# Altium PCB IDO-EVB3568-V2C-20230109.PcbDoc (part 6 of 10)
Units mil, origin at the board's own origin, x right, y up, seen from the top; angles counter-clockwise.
Board outline 5318 x 3544 mil, 2 copper layers (TOP, BOTTOM), stack 6.8 mil thick; 790 components, 626 nets, 2890 pads, 1922 vias.
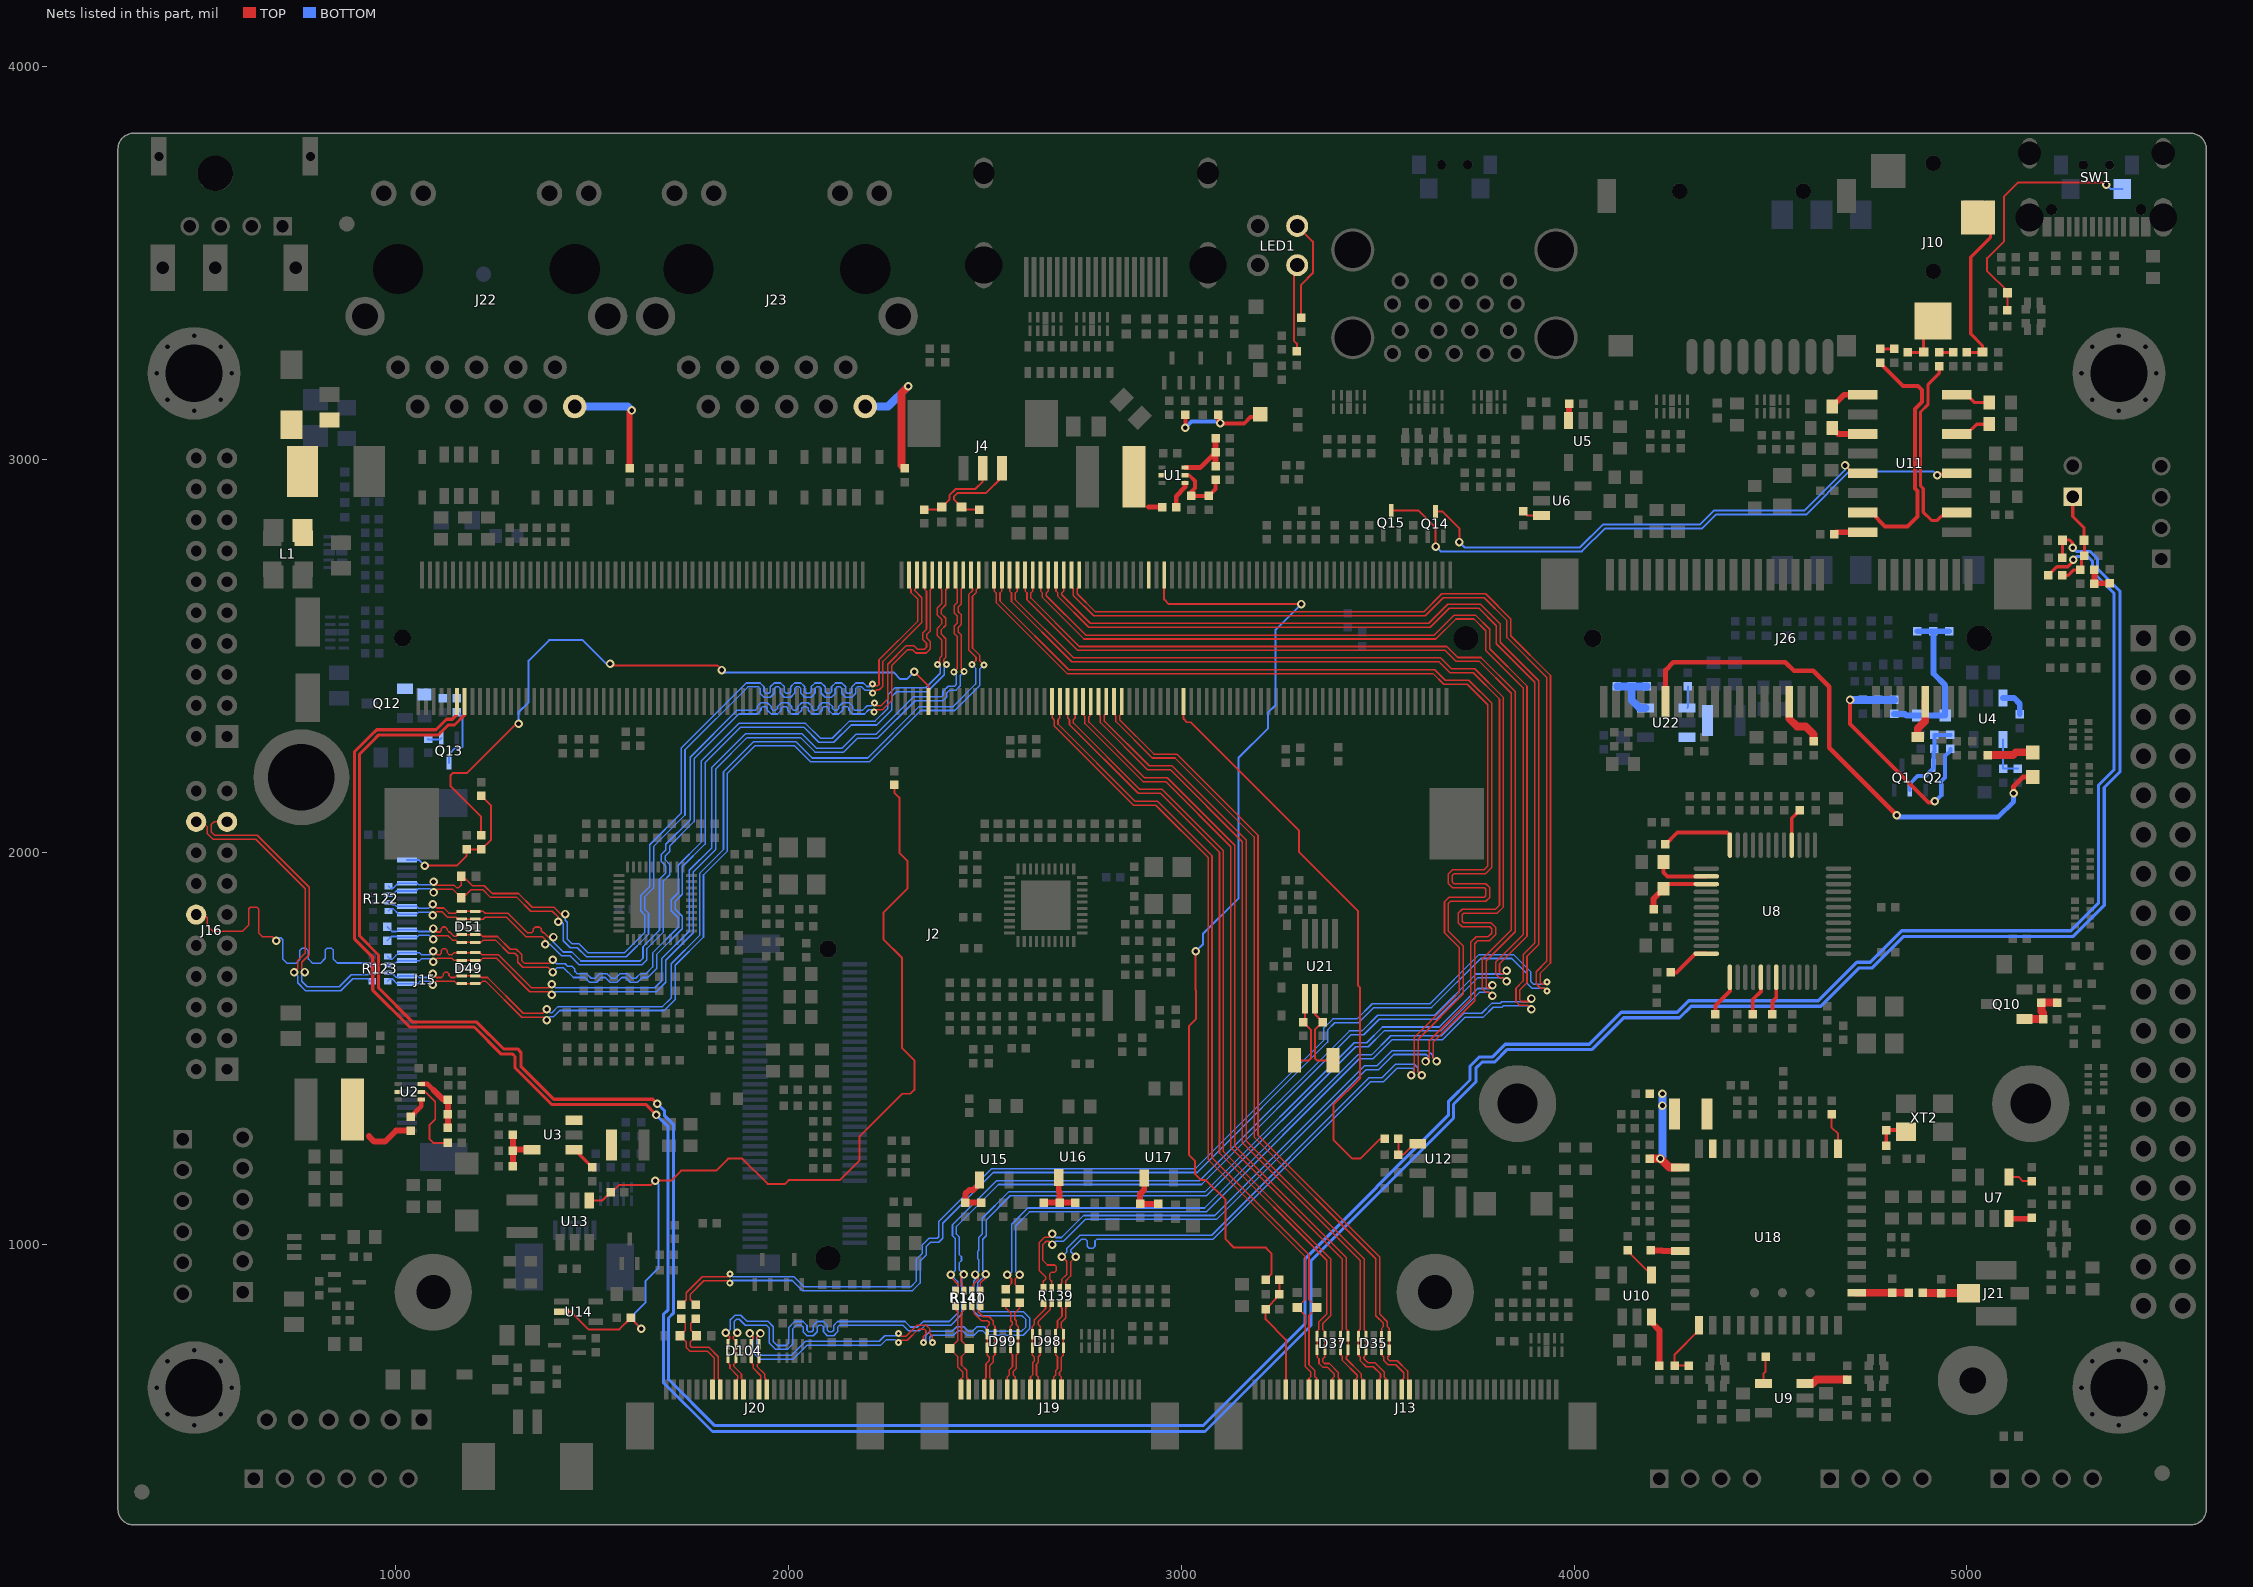
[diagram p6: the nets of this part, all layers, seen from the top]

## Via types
v1: diameter 21.65, hole 11.81, TOP to BOTTOM, 1878 vias
v2: diameter 17.72, hole 7.87, TOP to BOTTOM, 44 vias

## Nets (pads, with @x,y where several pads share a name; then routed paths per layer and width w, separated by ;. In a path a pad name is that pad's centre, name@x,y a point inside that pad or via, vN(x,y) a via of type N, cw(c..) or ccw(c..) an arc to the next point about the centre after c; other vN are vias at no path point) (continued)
LVDS_TX0_D2P: J16.12 R123.7 | length 771.1
  TOP w4: J16.12@491.26,1841.3 511.7,1841.3 519.63,1833.37 519.63,1813.37 534,1799 609,1799 625,1815 625,1856 629,1860 645.86,1860 650,1855.86 650,1795 660,1785 685,1785 v1(695,1775)
  BOTTOM w4: v1(695,1775) 702.35,1782.35 706.5,1782.35 711.93,1776.93 711.93,1727.93 722.36,1717.5 745.14,1717.5 755,1727.36 755,1750 760,1755 771,1755 777,1749 777,1728 787.5,1717.5 807.5,1717.5 820,1730 820,1751 824,1755 835.86,1755 840,1750.86 840,1728.36 850.36,1718 929,1718 934.16,1712.84 R123.7@939.32,1712.84
LVDS_TX0_D3N: J16.17 R123.6 | length 823.6
  TOP w4: J16.17@570,2077.52 536.52,2077.52 529.83,2070.83 529.83,2051.32 538.14,2043 647,2043 779,1911 779,1739 760,1720 760,1703 v1(768,1695)
  BOTTOM w4: v1(768,1695) 768,1694 760,1686 760,1671.5 774,1657.5 855.5,1657.5 886,1688 928,1688 933.16,1693.16 R123.6@939.32,1693.16
LVDS_TX0_D3P: J16.18 R123.5 | length 826.6
  TOP w4: J16.18@491.26,2077.52 506.48,2077.52 519.83,2064.17 519.83,2047.17 534,2033 642.86,2033 769,1906.86 769,1743.14 750,1724.14 750,1704.29 v1(740.36,1694.65)
  BOTTOM w4: v1(740.36,1694.65) 750,1685 750,1667.36 769.86,1647.5 859.64,1647.5 890.14,1678 928,1678 934.5,1671.5 R123.5@939.32,1671.5
MIC1_INN: C66.2 D97.2 J2.250 | length 8025.6
  TOP w8: 935.07,2296.39 894,2255.31 894,1780 941,1733 941,1649 1035,1555 1199,1555 1268,1486 1297,1486 1303,1480 1303,1451 1396,1358 1636,1358 v1(1663,1331) ; 935.08,2296.39 950.69,2312 1015.31,2312 1102,2312 1128.5,2338.5 1143.5,2338.5 1155.11,2350.11 J2.250@1155.11,2383.58 ; C66.2@5243.72,2750 5243.9,2750.18 D97.2@5243.9,2795 5262,2795 5270,2787 v1(5270,2775)
  BOTTOM w8: v1(1663,1331) 1693,1301 1693,835 1681,823 1681,649.86 1805.86,525 3060,525 3330,795 3330,960 3693,1323 3693,1358 3750,1415 3750,1450 3766,1466 3798,1466 3830,1498 4046,1498 4126.5,1578.5 4268.5,1578.5 4298,1608 4628,1608 4725,1705 4758,1705 4838,1785 5270,1785 5350,1865 5350,2165 5390,2205 5390,2665 5333,2722 5333,2747 5314,2766 5279,2766 v1(5270,2775)
MIC1_INP: C64.2 J2.248 | length 7964.5
  TOP w8: J2.248@1174.8,2383.58 1174.8,2349.8 1149,2324 1133.24,2324 1108.24,2299 1009.92,2299 956.08,2299 940.46,2283.38 907,2249.93 907,1787 955.5,1738.5 955.5,1654.5 1041.82,1568.18 1204.82,1568.18 1273.81,1499.19 1309.81,1499.19 1318,1491 1318,1455 1402,1371 1654,1371 v1(1665,1360) ; C64.2@5207.28,2705 5229.28,2727 5257,2727 5271,2741 v1(5271,2745)
  BOTTOM w8: v1(1665,1360) 1684,1341 1684,1329 1707,1306 1707,827 1694,814 1694,658.07 1812.07,540 3055,540 3315,800 3315,965 3680,1330 3680,1365 3735,1420 3735,1455 3759,1479 3792.61,1479 3824.61,1511 4039,1511 4120.49,1592.49 4262.49,1592.49 4292,1622 4622,1622 4720,1720 4754,1720 4834,1800 5265,1800 5335,1870 5335,2170 5375,2210 5375,2660 5320,2715 5320,2741 5308,2753 5279,2753 v1(5271,2745)
MIPI_CSI_CLK0N: D99.1 D99.10 J19.17 R148.2 | length 236.4
  TOP w4: J19.17@2576.42,632.01 2576.42,663.84 2571.57,668.68 2571.57,677.43 2580,685.86 2580,720 2584.37,724.37 D99.10@2584.37,737.78 D99.1@2584.37,772.22 2584.37,792.44 2579.53,797.28 2579.53,807.08 2575.5,811.11 2575.5,826.62 2588,839.12 R148.2@2588,852.28
MIPI_CSI_CLK0P: D99.2 D99.9 J19.18 R147.2 | length 236.9
  TOP w4: R147.2@2553,852.28 2553,839 2553.12,839 2565.5,826.62 2565.5,806.96 2569.53,802.94 2569.53,797.28 2564.68,792.43 D99.2@2564.68,772.22 D99.9@2564.68,737.78 2564.68,725.32 2570,720 2570,690 2561.57,681.58 2561.57,668.68 2556.73,663.84 J19.18@2556.73,632.01
MIPI_CSI_CLK1N: D105.1 J20.17 R158.2 | length 255.6
  TOP w4: R158.2@1763,812.28 1751,800.28 1751,783.1 D105.1@1765.1,769 1749,752.9 1749,743 1753,739 1797.45,739 1820.87,715.59 1820.87,660.13 1825.71,655.29 J20.17@1825.71,632.01
MIPI_CSI_CLK1P: D106.1 J20.18 R157.2 | length 255.2
  TOP w4: R157.2@1726,812.28 1726,812 1737,801 1737,783.1 D106.1@1722.9,769 1739,752.9 1739,738.86 1748.86,729 1793.31,729 1810.87,711.44 1810.87,659.87 1806.02,655.02 J20.18@1806.02,632.01
MIPI_CSI_D0N: D98.1 D98.10 J19.11 R139.8 | length 234.4
  TOP w4: J19.11@2694.53,632.01 2694.53,663.84 2689.69,668.68 2689.69,675.54 2694.53,680.38 2694.53,714.53 2699.37,719.37 D98.10@2699.37,737.78 D98.1@2699.37,772.22 2699.37,784.63 2694.53,789.47 2694.53,802.94 2706,814.41 2706,840 2711.5,845.5 R139.8@2711.5,851.32
MIPI_CSI_D0P: D98.2 D98.9 J19.12 R139.7 | length 234.6
  TOP w4: J19.12@2674.84,632.01 2674.84,663.84 2679.69,668.68 2679.69,679.69 2684.53,684.53 2684.53,715.47 2679.68,720.32 D98.9@2679.68,737.78 D98.2@2679.68,772.22 2679.68,784.68 2684.53,789.53 2684.53,807.08 2696,818.55 2696,839 2689.84,845.16 R139.7@2689.84,851.32
MIPI_CSI_D1N: D98.4 D98.7 J19.14 R139.6 | length 241.4
  TOP w4: J19.14@2635.47,632.01 2635.47,663.84 2631,668.31 2631,696 2635.47,700.48 2635.47,715.48 2640.32,720.32 D98.7@2640.32,737.78 D98.4@2640.32,772.22 2640.32,792.44 2635.47,797.28 2635.47,804.86 2666,835.38 2666,847.16 R139.6@2670.16,851.32
MIPI_CSI_D1P: D98.5 D98.6 J19.15 R139.5 | length 241.4
  TOP w4: J19.15@2615.79,632.01 2615.79,663.84 2621,669.05 2621,700.14 2625.47,704.62 2625.47,714.52 2620.63,719.37 D98.6@2620.63,737.78 D98.5@2620.63,772.22 2620.63,792.43 2625.47,797.28 2625.47,809 2654,837.52 2654,845.82 R139.5@2648.5,851.32
MIPI_CSI_D2N: D99.4 D99.7 J19.20 R140.8 | length 248.6
  TOP w4: R140.8@2488.5,844.32 2488.5,840.5 2482.87,834.87 2482.87,829.21 2495.14,816.94 2510.62,816.94 2520.47,807.08 2520.47,797.28 2525.32,792.44 D99.4@2525.32,772.22 D99.7@2525.32,737.78 2525.32,720.32 2520.47,715.48 2520.47,701.33 2512.52,693.38 2512.52,662.48 2517.36,657.64 J19.20@2517.36,632.01
MIPI_CSI_D2N_: D104.1 D104.10 J20.11 R141.5 | length 1209
  TOP w4: v1(1928.17,774.65) 1919.53,766 1919.53,761.85 1924.37,757 D104.1@1924.37,747.22 D104.10@1924.37,712.78 1924.37,699.37 1919.53,694.53 1919.53,690.62 1938.98,671.16 1938.98,661.02 1943.82,656.18 J20.11@1943.82,632.01 ; v2(2280,774.72) 2280,773.14 2286,767.14 2298,767.14 2326.55,795.69 2349.78,795.69 2359.64,785.84 2359.64,773.68 2366,767.32 v2(2366,751.86)
  BOTTOM w4: v1(1928.17,774.65) 1919,765.48 1919,731 1931,719 2006.86,719 2042.86,755 2230.64,755 2244.64,769 2273,769 2278.72,774.72 v2(2280,774.72) ; v2(2366,751.86) 2363.14,751.86 2359,756 2359,765 2364,770 2419.98,770 2431.98,782 2441.84,782 2453.84,770 2471.98,770 2483.98,782 2493.84,782 2505.84,770 2597,770 2614,787 2614,795.28 2614,814 2598.19,829.81 2556.55,829.81 ; R141.5@2486.5,845.32 2486.5,833.81 2490.48,829.83 2499.98,829.83 ; 2500,829.81 2533.45,829.81 ; 2533.47,829.83 2556.53,829.83
MIPI_CSI_D2P: D99.5 D99.6 J19.21 R140.7 | length 248.8
  TOP w4: R140.7@2466.84,844.32 2466.84,838.16 2472.87,832.13 2472.87,825.07 2491,806.94 2506.47,806.94 2510.47,802.94 2510.47,797.28 2505.63,792.43 D99.5@2505.63,772.22 D99.6@2505.63,737.78 2505.63,719.37 2510.47,714.52 2510.47,705.48 2502.52,697.52 2502.52,662.52 2497.68,657.68 J19.21@2497.68,632.01
MIPI_CSI_D2P_: D104.2 D104.9 J20.12 R141.6 | length 1211.6
  TOP w4: v1(1900.88,774.65) 1909.53,766 1909.53,762 1904.68,757.16 D104.2@1904.68,747.22 D104.9@1904.68,712.78 1904.68,700.32 1909.53,695.47 1909.53,686.47 1928.98,667.02 1928.98,658.98 1924.13,654.13 J20.12@1924.13,632.01 ; v2(2280,752) 2285.14,757.14 2302.14,757.14 2330.69,785.69 2345.64,785.69 2349.64,781.69 2349.64,773.68 2343.28,767.32 v2(2343.28,751.86)
  BOTTOM w4: v1(1900.88,774.65) 1909,766.53 1909,726.86 1926.86,709 2011,709 2047,745 2234.79,745 2248.79,759 2271,759 2278,752 v2(2280,752) ; v2(2343.28,751.86) 2349,757.58 2349,769.14 2359.86,780 2415.84,780 2427.84,792 2445.98,792 2457.98,780 2467.84,780 2479.84,792 2497.98,792 2509.98,780 2592.86,780 2604,791.14 2604,809.86 2594.05,819.81 2552.41,819.81 ; R141.6@2464.84,845.32 2464.84,838.16 2483.17,819.83 2495.84,819.83 ; 2495.86,819.81 2537.59,819.81 ; 2537.61,819.83 2552.39,819.83
MIPI_CSI_D3N: D100.1 J19.23 R140.6 | length 239.5
  TOP w4: R140.6@2447.16,844.32 2447.16,834.16 2440,827 2440,756 2459.9,736.1 D100.1@2460,736.1 2440,716.1 2440,694.14 2453.47,680.68 2453.47,661.54 2458.31,656.69 J19.23@2458.31,632.01
MIPI_CSI_D3N_: D104.4 D104.7 J20.14 R141.7 | length 998.1
  TOP w4: v1(1869.32,776.43) 1859.27,766.38 1859.27,760.73 1865.32,754.68 D104.4@1865.32,747.22 D104.7@1865.32,712.78 1865.32,700.32 1860.47,695.48 1860.47,690.67 1879.92,671.22 1879.92,660.08 1884.76,655.24 J20.14@1884.76,632.01
  BOTTOM w4: v1(1869.32,776.43) 1869.32,778.68 1861.45,786.54 1861.45,805.31 1867.24,811.09 1873.89,811.09 1889.48,795.5 1943.36,795.5 1951,787.86 1951,749.86 1966.86,734 1997.14,734 2010,746.86 2010,785.86 2019.14,795 2032.59,795 2036.59,791 2036.59,778.86 2046.45,769 2062.74,769 2072.59,778.86 2072.59,791 2076.59,795 2084.59,795 2088.59,791 2088.59,778.86 2098.45,769 2114.74,769 2124.59,778.86 2124.59,791 2128.59,795 2292,795 2306,781 2333,781 2347,795 2412.69,795 2441,823.31 2441,835 2445.16,839.16 R141.7@2445.16,845.32
MIPI_CSI_D3P: D101.1 J19.24 R140.5 | length 238.4
  TOP w4: R140.5@2425.5,844.32 2425.5,834.5 2430,830 2430,756 2410.1,736.1 D101.1@2410,736.1 2430,716.1 2430,690 2443.47,676.53 2443.47,663.46 2438.62,658.62 J19.24@2438.62,632.01
MIPI_CSI_D3P_: D104.5 D104.6 J20.15 R141.8 | length 1001.7
  TOP w4: v1(1839.78,776.32) 1849.27,766.83 1849.27,760.27 1845.63,756.63 D104.5@1845.63,747.22 D104.6@1845.63,712.78 1845.63,699.37 1850.47,694.52 1850.47,686.52 1869.92,667.08 1869.92,659.92 1865.08,655.08 J20.15@1865.08,632.01
  BOTTOM w4: v1(1839.78,776.32) 1842.88,776.32 1851.45,784.89 1851.45,809.46 1857.31,815.31 1863.09,821.09 1878.03,821.09 1893.63,805.5 1947.5,805.5 1961,792 1961,754 1971,744 1993,744 2000,751 2000,790 2015,805 2036.74,805 2046.59,795.14 2046.59,783 2050.59,779 2058.59,779 2062.59,783 2062.59,795.14 2072.45,805 2088.74,805 2098.59,795.14 2098.59,783 2102.59,779 2110.59,779 2114.59,783 2114.59,795.14 2124.45,805 2296.14,805 2310.14,791 2328.86,791 2342.86,805 2408.55,805 2431,827.45 2431,835 2423.5,842.5 R141.8@2423.5,845.32
MIPI_CSI_RX_CLK0N: J2.103 R148.1 | length 4034.2
  TOP w4: v1(2587.78,924.5) 2587.78,924 2577.39,913.61 2577.39,898.33 R148.1@2588,887.72 ; J2.103@2680.7,2706.42 2680.7,2665.14 2685.55,2660.3 2685.55,2651.45 2764,2573 3634,2573 3682.28,2621.28 3757.58,2621.28 3802,2576.86 3802,2530.86 3900,2432.86 3900,1769.14 3870,1739.14 3870,1672 3852,1654 3852,1619.86 3861.86,1610 3882,1610 v1(3891.5,1600.5)
  BOTTOM w4: v1(2587.78,924.5) 2584.5,924.5 2578,931 2578,1048.86 2613.14,1084 3063.14,1084 3453.14,1474 3488.14,1474 3537.07,1522.93 3665.8,1522.93 3723.04,1580.17 3769.17,1580.17 3794,1605 3816.14,1605 3820.14,1609 3883,1609 v1(3891.5,1600.5)
MIPI_CSI_RX_CLK0P: J2.101 R147.1 | length 4035.8
  TOP w4: R147.1@2553,887.72 2567.39,902.11 2567.39,913.61 v1(2557,924) ; J2.101@2700.39,2706.42 2700.39,2665.14 2695.55,2660.3 2695.55,2655.6 2768.14,2583 3629.86,2583 3678.13,2631.28 3761.72,2631.28 3764.65,2628.35 3812,2581 3812,2535 3910,2437 3910,1765 3880,1735 3880,1667.86 3862,1649.86 3862,1624 3866,1620 3884,1620 v1(3891.5,1627.5)
  BOTTOM w4: v1(2557,924) 2561,924 2568,931 2568,1053 2609,1094 3059,1094 3449,1484 3484,1484 3532.93,1532.93 3661.65,1532.93 3718.9,1590.17 3765.03,1590.17 3789.86,1615 3812,1615 3816,1619 3883,1619 v1(3891.5,1627.5)
MIPI_CSI_RX_CLK1N: J2.99 R158.1 | length 4965.9
  TOP w4: R158.1@1763,847.72 1749,861.72 1749,874 1784,909 1843.46,909 v2(1850,903) ; J2.99@2720.07,2706.42 2720.07,2675.84 2724.91,2671 2724.91,2654.09 2777,2602 3621,2602 3667,2648 3771,2648 3829,2590 3829,2546.86 3930,2445.86 3930,1722.14 3903.5,1695.64 3903.5,1665.36 3914.86,1654 3925,1654 3930.97,1648.03 v2(3930.97,1647)
  BOTTOM w4: v2(1850,903) 1856.5,909.5 2008.94,909.5 2034.61,883.83 2315.39,883.83 2334.5,902.94 2334.5,958.71 2350.5,974.71 2350.5,996.36 2361.14,1007 2382.14,1007 2392,1016.86 2392,1055.44 2521.06,1184.5 3040.06,1184.5 3372.17,1516.61 3372.17,1547.39 3390.29,1565.5 3451.08,1565.5 3490.08,1604.5 3637.06,1604.5 3762.06,1729.5 3841.36,1729.5 3880,1690.86 3880,1666.28 3892.73,1653.55 3908.99,1653.53 3925.48,1653.53 3930.97,1648.02 v2(3930.97,1647)
MIPI_CSI_RX_CLK1P: J2.97 R157.1 | length 4965.2
  TOP w4: R157.1@1726,847.72 1739,860.72 1739,878.14 1779.86,919 1844.59,919 v2(1851,926) ; J2.97@2739.76,2706.42 2739.76,2676 2734.91,2671.16 2734.91,2658.23 2781.14,2612 3616.86,2612 3662.86,2658 3775.14,2658 3839,2594.14 3839,2551 3940,2450 3940,1718 3913.5,1691.5 3913.5,1669.5 3919,1664 3926,1664 3931,1669 v2(3931,1670)
  BOTTOM w4: v2(1851,926) 1857.5,919.5 2013.08,919.5 2038.75,893.83 2311.25,893.83 2324.5,907.08 2324.5,962.86 2340.5,978.86 2340.5,1000.5 2357,1017 2378,1017 2382,1021 2382,1059.58 2516.92,1194.5 3035.92,1194.5 3362.17,1520.75 3362.17,1551.53 3386.14,1575.5 3446.94,1575.5 3485.94,1614.5 3632.92,1614.5 3757.92,1739.5 3845.5,1739.5 3890,1695 3890,1670.42 3896.87,1663.55 3909,1663.53 3924.51,1663.53 v2(3931,1670)
MIPI_CSI_RX_D0N: J2.119 R139.1 | length 3949.3
  TOP w4: J2.119@2523.22,2706.42 2523.22,2665.14 2528.06,2660.3 2528.06,2635.79 2708.86,2455 3640.86,2455 3667.86,2428 3727.86,2428 3780,2375.86 3780,1965 3770,1955 3689.86,1955 3680,1945.14 3680,1919.86 3689.86,1910 3771,1910 3775,1906 3775,1889 3771,1885 3680.86,1885 3670,1874.14 3670,1795 3708,1757 3708,1643 3593,1528 3593,1440 v1(3585,1432) ; R139.1@2711.5,890.68 2711.5,894.5 2705,901 2705,907.86 2717.81,920.67 2717.81,956.81 v1(2731.15,970.15)
  BOTTOM w4: v1(2731.15,970.15) 2718.5,982.79 2718.5,987.36 2746.14,1015 2755,1015 2760,1010 2760,997 2765.17,991.83 2774.83,991.83 2780,997 2780,1010 2785,1015 3081.14,1015 3482.14,1416 3515.14,1416 3549.14,1450 3589,1450 3593,1446 3593,1440 v1(3585,1432)
MIPI_CSI_RX_D0P: J2.117 R139.2 | length 3947.7
  TOP w4: J2.117@2542.91,2706.42 2542.91,2665.14 2538.06,2660.3 2538.06,2639.94 2713,2465 3645,2465 3672,2438 3732,2438 3790,2380 3790,1960.86 3774.14,1945 3694,1945 3690,1941 3690,1924 3694,1920 3775.14,1920 3785,1910.14 3785,1884.86 3775.14,1875 3685,1875 3680,1870 3680,1799.14 3718,1761.14 3718,1638.86 3603,1523.86 3603,1441 v1(3612,1432) ; R139.2@2689.84,890.68 2689.84,897.84 2695,903 2695,912 2707.81,924.81 2707.81,958.19 v1(2695.86,970.15)
  BOTTOM w4: v1(2695.86,970.15) 2708.5,982.79 2708.5,991.5 2742,1025 3077,1025 3478,1426 3511,1426 3545,1460 3593.14,1460 3603,1450.14 3603,1441 v1(3612,1432)
MIPI_CSI_RX_D1N: J2.115 R139.3 | length 3952.9
  TOP w4: J2.115@2562.59,2706.42 2562.59,2665.14 2567.43,2660.3 2567.43,2638.42 2720.86,2485 3655.86,2485 3683.86,2457 3743,2457 3810,2390 3810,1865 3800,1855 3715,1855 3705,1845 3705,1820 3715,1810 3785,1810 3790,1805 3790,1794 3781,1785 3750.86,1785 3737,1771.14 3737,1626.14 3631,1520.14 3631,1476.49 v1(3621.68,1467.16) ; R139.3@2670.16,890.68 2670.16,907.36 2664.33,913.19 2664.33,926.33 2669,931 2678,931 2681,934 2681,946 2678,949 2659,949 2647.5,960.5 2647.5,1001.36 2655.64,1009.5 2662.5,1009.5 v1(2671,1001)
  BOTTOM w4: v1(2671,1001) 2679,1009 2699,1009 2755,1065 3089.14,1065 3470.14,1446 3502,1446 3541,1485 3623.86,1485 3629.86,1479 3629.86,1475.34 v1(3621.68,1467.16)
MIPI_CSI_RX_D1P: J2.113 R139.4 | length 3955.3
  TOP w4: J2.113@2582.28,2706.42 2582.28,2665.14 2577.43,2660.3 2577.43,2642.57 2725,2495 3660,2495 3688,2467 3747.14,2467 3820,2394.14 3820,1860.86 3804.14,1845 3719.14,1845 3715,1840.86 3715,1824.14 3719.14,1820 3789.14,1820 3800,1809.14 3800,1789.86 3785.14,1775 3755,1775 3747,1767 3747,1622 3641,1516 3641,1476.49 v1(3649.65,1467.84) ; R139.4@2648.5,890.68 2648.5,907.37 2654.33,913.19 2654.33,918.53 2637.5,935.36 2637.5,1005.5 2651.5,1019.5 2662.5,1019.5 v1(2671,1028)
  BOTTOM w4: v1(2671,1028) 2680,1019 2694.86,1019 2750.86,1075 3085,1075 3466,1456 3497.86,1456 3536.86,1495 3628,1495 3639.86,1483.14 3639.86,1477.63 v1(3649.65,1467.84)
MIPI_CSI_RX_D2N: J2.111 R140.1 R141.4 | length 3991
  TOP w4: R140.1@2488.5,883.68 2488.07,884.11 2488.07,902.93 2499,913.86 2499,921.87 v1(2502.18,925.05) ; J2.111@2601.96,2706.42 2601.96,2665.14 2606.8,2660.3 2606.8,2643.2 2736,2514 3671.86,2514 3699.86,2486 3759,2486 3840,2405 3840,1802 3766,1728 3766,1653 3775.86,1643.14 3783.37,1643.14 v1(3792.16,1634.36)
  BOTTOM w4: R141.4@2486.5,884.68 2481,890.18 2481,903.87 v1(2502.18,925.05) 2502.18,928.18 2494,936.36 2494,1014.64 2502.83,1023.47 2502.83,1063.68 2564.14,1125 3064.14,1125 3444.14,1505 3476.14,1505 3516.14,1545 3661,1545 3759,1643 3783.51,1643 v1(3792.16,1634.36)
MIPI_CSI_RX_D2P: J2.109 R140.2 R141.3 | length 3990.8
  TOP w4: R140.2@2466.84,883.68 2470,886.84 2470,899 2482.35,911.35 2482.35,918.65 2476.35,924.65 v1(2475.53,924.65) ; J2.109@2621.65,2706.42 2621.65,2665.14 2616.8,2660.3 2616.8,2647.34 2740.14,2524 3676,2524 3704,2496 3763.14,2496 3850,2409.14 3850,1797.86 3776,1723.86 3776,1657.14 3780,1653.14 3783.66,1653.14 v1(3792.16,1661.65)
  BOTTOM w4: R141.3@2464.84,884.68 2464.84,888.84 2471,895 2471,908.01 2476.35,913.36 2476.35,923.83 v1(2475.53,924.65) 2484,933.12 2484,962.41 2481,965.41 2481,983.41 2484,986.41 2484,1018.79 2492.83,1027.61 2492.83,1067.83 2560,1135 3060,1135 3440,1515 3472,1515 3512,1555 3656.86,1555 3754.86,1653 3783.51,1653 v1(3792.16,1661.65)
MIPI_CSI_RX_D3N: J2.107 R140.3 R141.2 | length 4139.2
  TOP w4: v1(2446.22,924.82) 2445.82,924.82 2437.64,916.64 2437.64,907.36 2442,903 2442,895 2447.16,889.84 R140.3@2447.16,883.68 ; J2.107@2641.33,2706.42 2641.33,2665.14 2646.18,2660.3 2646.18,2648.82 2752,2543 3648,2543 3699,2594 3744.86,2594 3775,2563.86 3775,2514 3870,2419 3870,1790 3800,1720 3800,1690.16 3804.93,1685.23 3809.86,1680.3 3819.05,1680.3 v1(3828,1671.36)
  BOTTOM w4: R141.2@2445.16,884.68 2445.16,888.11 2440,893.26 2440,917.83 2446.22,924.04 v1(2446.22,924.82) 2434,937.04 2434,953.86 2440,959.86 2440,969.86 2434,975.86 2434,1020.78 2427.17,1027.61 2427.17,1047.17 2534,1154 3051.14,1154 3432.14,1535 3464.14,1535 3504.14,1575 3649.14,1575 3754.14,1680 3819.36,1680 v1(3828,1671.36)
MIPI_CSI_RX_D3P: J2.105 R140.4 R141.1 | length 4140.5
  TOP w4: v1(2413.04,924.04) 2415,922.08 2415,915.86 2432,898.86 2432,890.18 R140.4@2425.5,883.68 ; J2.105@2661.02,2706.42 2661.02,2665.14 2656.18,2660.3 2656.18,2652.97 2756.14,2553 3643.86,2553 3694.86,2604 3749,2604 3785,2568 3785,2518.14 3880,2423.14 3880,1785.86 3810,1715.86 3810,1694.3 3814,1690.3 3819.66,1690.3 v1(3828,1698.65)
  BOTTOM w4: R141.1@2423.5,884.68 2430,891.18 2430,907.08 v1(2413.04,924.04) 2424,935 2424,1016.64 2417.17,1023.47 2417.17,1051.32 2529.86,1164 2538.14,1164 3047,1164 3428,1545 3460,1545 3500,1585 3645,1585 3750,1690 3819.35,1690 v1(3828,1698.65)
MIPI_DSI_TX0_CLKN: D51.2 D51.9 J2.133 J15.27 R127.1 | length 2434.4
  TOP w4: v1(1094.64,1805.76) 1103.4,1797 1112,1797 1115,1800 1115,1805 1119.67,1809.67 1125.33,1809.67 1130,1805 1130,1802 1135,1797 1137.14,1797 1147.74,1786.4 1153.4,1786.4 1157.32,1790.32 D51.9@1167.78,1790.32 D51.2@1202.22,1790.32 1215.68,1790.32 1220.53,1785.47 1258.67,1785.47 1291.08,1753.06 1306.43,1753.06 1320.07,1739.42 1320.07,1724.08 1327.14,1717 1390,1717 v1(1399,1726) ; v2(2379.28,2478) 2385,2483.72 2385,2495 2390.27,2500.27 2390.27,2539.8 2378,2552.07 2378,2569.95 2390.27,2582.22 2390.27,2591.8 2378,2604.07 2378,2621.95 2390.27,2634.22 2390.27,2667.73 2385.43,2672.57 J2.133@2385.43,2706.42
  BOTTOM w4: R127.1@977.72,1810 989.61,1798.11 1001.11,1798.11 1005.95,1802.95 J15.27@1027.99,1802.95 1052.05,1802.95 1056.89,1798.11 1087,1798.11 v1(1094.64,1805.76) ; v1(1399,1726) 1409,1716 1431,1716 1437,1710 1448,1710 1455,1703 1455,1697 1461,1691 1485,1691 1497,1679 1506.86,1679 1518.86,1691 1537,1691 1549,1679 1558.86,1679 1570.86,1691 1589,1691 1601,1679 1610.86,1679 1622.86,1691 1637,1691 1653.5,1707.5 1653.5,1743.64 1719,1809.14 1719,1833 1701,1851 1701,1879 1719,1897 1719,1967 1777,2025 1777,2232 1873,2328 2043,2328 2081,2290 2110.86,2290 2154.86,2334 2220,2334 2252,2366 2252,2400.14 2270.86,2419 2349,2419 2386,2456 2386,2471.28 v2(2379.28,2478)
MIPI_DSI_TX0_CLKP: D51.1 D51.10 J2.131 J15.26 R126.1 | length 2434
  TOP w4: v1(1094.64,1778.46) 1103.18,1787 1133,1787 1143.6,1776.4 1152.6,1776.4 1158.37,1770.63 D51.10@1167.78,1770.63 D51.1@1202.22,1770.63 1216.63,1770.63 1221.47,1775.47 1254.53,1775.47 1286.94,1743.06 1302.29,1743.06 1310.07,1735.28 1310.07,1719.93 1323,1707 1387,1707 v1(1399,1695) ; v2(2402,2478) 2395,2485 2395,2490.86 2400.27,2496.13 2400.27,2543.95 2388,2556.22 2388,2565.8 2400.27,2578.07 2400.27,2595.95 2388,2608.22 2388,2617.8 2400.27,2630.07 2400.27,2668.27 2405.11,2673.11 J2.131@2405.11,2706.42
  BOTTOM w4: R126.1@977.72,1775 988.25,1785.53 1002.47,1785.53 1004.73,1783.27 J15.26@1027.99,1783.27 1053.27,1783.27 1058.11,1788.11 1085,1788.11 v1(1094.64,1778.46) ; v1(1399,1695) 1410,1706 1426.86,1706 1451.86,1681 1480.86,1681 1492.86,1669 1511,1669 1523,1681 1532.86,1681 1544.86,1669 1563,1669 1575,1681 1584.86,1681 1596.86,1669 1615,1669 1627,1681 1641.14,1681 1663.5,1703.36 1663.5,1739.5 1729,1805 1729,1837.14 1711,1855.14 1711,1874.86 1729,1892.86 1729,1962.86 1787,2020.86 1787,2227.86 1877.14,2318 2038.86,2318 2076.86,2280 2115,2280 2159,2324 2224.14,2324 2262,2361.86 2262,2396 2275,2409 2353.14,2409 2396,2451.86 2396,2472 v2(2402,2478)
MIPI_DSI_TX0_D0N: D53.1 J2.141 J15.33 R122.1 | length 2441.2
  TOP w4: v1(1095.64,1924.87) 1104.29,1916.22 1148.03,1916.22 1154.3,1909.95 1159.95,1909.95 1166.1,1916.1 D53.1@1166.1,1939 1170.57,1939 1194.57,1915 1225,1915 1245,1895 1312,1895 1347,1860 1402.14,1860 1419.5,1842.65 v1(1431.24,1842.65) ; v2(2212.92,2428.69) 2213.31,2428.69 2218.5,2423.5 2226.36,2423.5 2230,2427.14 2230,2490 2329,2589 2329,2644 2311.53,2661.47 2311.53,2669.47 2306.69,2674.31 J2.141@2306.69,2706.42
  BOTTOM w4: R122.1@980.68,1913.5 986.26,1907.92 991.92,1907.92 1005.06,1921.06 J15.33@1027.99,1921.06 1053.94,1921.06 1058.17,1916.83 1087.61,1916.83 v1(1095.64,1924.87) ; v1(1431.24,1842.65) 1431.24,1826.76 1436,1822 1436,1779 1448,1767 1466,1767 1489,1744 1582,1744 1633,1795 1633,1841 1623,1851 1623,1890 1646,1913 1646,2019 1726,2099 1726,2265 1892,2431 1927.19,2431 1937.05,2421.14 1937.05,2409 1941.05,2405 1949.05,2405 1953.05,2409 1953.05,2421.14 1962.91,2431 1979.19,2431 1989.05,2421.14 1989.05,2409 1993.05,2405 2001.05,2405 2005.05,2409 2005.05,2421.14 2014.91,2431 2031.19,2431 2041.05,2421.14 2041.05,2409 2045.05,2405 2053.05,2405 2057.05,2409 2057.05,2421.14 2066.91,2431 2083.19,2431 2093.05,2421.14 2093.05,2409 2097.05,2405 2105.05,2405 2109.05,2409 2109.05,2421.14 2118.91,2431 2135.19,2431 2145.05,2421.14 2145.05,2409 2149.05,2405 2157.05,2405 2161.05,2409 2161.05,2421.14 2170.91,2431 2190.14,2431 2199.14,2422 2206.23,2422 v2(2212.92,2428.69)
MIPI_DSI_TX0_D0P: D52.1 J2.139 J15.32 R122.2 | length 2433.3
  TOP w4: v1(1095.64,1897.58) 1104.29,1906.22 1143.88,1906.22 D52.1@1166.1,1884 1170.57,1884 1191.57,1905 1220.86,1905 1240.86,1885 1307.86,1885 1342.86,1850 1398,1850 1413,1835 v1(1413,1823) ; v2(2214,2406) 2216.95,2406 2224.45,2413.5 2230.5,2413.5 2240,2423 2240,2485.86 2339,2584.86 2339,2648.14 2321.53,2665.61 2321.53,2669.53 2326.37,2674.37 J2.139@2326.37,2706.42
  BOTTOM w4: R122.2@980.68,1891.84 990.84,1891.84 1000.38,1901.38 J15.32@1027.99,1901.38 1051.38,1901.38 1056.83,1906.83 1086.39,1906.83 v1(1095.64,1897.58) ; v1(1413,1823) 1420.86,1823 1426,1817.86 1426,1774.86 1443.86,1757 1461.86,1757 1484.86,1734 1586.14,1734 1643,1790.86 1643,1845.14 1633,1855.14 1633,1885.86 1656,1908.86 1656,2014.86 1736,2094.86 1736,2260.86 1896.14,2421 1923.05,2421 1927.05,2417 1927.05,2404.86 1936.91,2395 1953.19,2395 1963.05,2404.86 1963.05,2417 1967.05,2421 1975.05,2421 1979.05,2417 1979.05,2404.86 1988.91,2395 2005.19,2395 2015.05,2404.86 2015.05,2417 2019.05,2421 2027.05,2421 2031.05,2417 2031.05,2404.86 2040.91,2395 2057.19,2395 2067.05,2404.86 2067.05,2417 2071.05,2421 2079.05,2421 2083.05,2417 2083.05,2404.86 2092.91,2395 2109.19,2395 2119.05,2404.86 2119.05,2417 2123.05,2421 2131.05,2421 2135.05,2417 2135.05,2404.86 2144.91,2395 2161.19,2395 2171.05,2404.86 2171.05,2417 2175.05,2421 2186,2421 2195,2412 2208,2412 v2(2214,2406)
MIPI_DSI_TX0_D1N: D51.5 D51.6 J2.137 J15.30 R122.3 | length 2408.2
  TOP w4: v1(1093.65,1867.81) 1103.46,1858 1122,1858 1135,1845 1152,1845 1156.37,1849.37 D51.6@1167.78,1849.37 D51.5@1202.22,1849.37 1222.43,1849.37 1227.28,1844.53 1285.47,1844.53 1335,1795 1345,1795 1350,1800 1350,1805 1354.67,1809.67 1365.33,1809.67 1370,1805 1370,1800 1375,1795 1377,1795 1387.99,1784.01 v1(1401.01,1784.01) ; v2(2218,2380) 2225,2373 2235,2373 2252,2390 2252,2479 2299,2526 2319,2526 2327.57,2517.43 2346.28,2517.43 2350.9,2522.04 2350.9,2532.1 2341.5,2541.5 2341.5,2558.6 2350.9,2568 2350.9,2665.1 2346.06,2669.94 J2.137@2346.06,2706.42
  BOTTOM w4: R122.3@980.68,1872.16 984.84,1872.16 990,1867 996.24,1867 1001.24,1862.01 J15.30@1027.99,1862.01 1052.99,1862.01 1057.84,1857.16 1083,1857.16 v1(1093.65,1867.81) ; v1(1401.01,1784.01) 1400.1,1772.13 1426.23,1746 1448,1746 1471,1723 1621.86,1723 1629,1730.14 1629,1759.14 1671,1801.14 1671,1931.14 1687,1947.14 1687,1964.86 1676,1975.86 1676,1995 1687,2006 1687,2020.14 1749,2082.14 1749,2242.14 1868.86,2362 1915.54,2362 1919.54,2366 1919.54,2371.14 1929.39,2381 1945.68,2381 1955.54,2371.14 1955.54,2366 1959.54,2362 1967.54,2362 1971.54,2366 1971.54,2371.14 1981.39,2381 1997.68,2381 2007.54,2371.14 2007.54,2366 2011.54,2362 2019.54,2362 2023.54,2366 2023.54,2371.14 2033.39,2381 2049.68,2381 2059.54,2371.14 2059.54,2366 2063.54,2362 2071.54,2362 2075.54,2366 2075.54,2371.14 2085.39,2381 2101.68,2381 2111.54,2371.14 2111.54,2366 2115.54,2362 2123.54,2362 2127.54,2366 2127.54,2371.14 2137.39,2381 2153.68,2381 2163.54,2371.14 2163.54,2366 2167.54,2362 2189,2362 2200,2373 2211.14,2373 2216.71,2378.57 2216.71,2378.71 v2(2218,2380)
MIPI_DSI_TX0_D1P: D51.4 D51.7 J2.135 J15.29 R122.4 | length 2407.2
  TOP w4: v1(1093.65,1839.52) 1102.13,1848 1117.86,1848 1130.86,1835 1152,1835 1157.32,1829.68 D51.7@1167.78,1829.68 D51.4@1202.22,1829.68 1222.44,1829.68 1227.28,1834.53 1281.33,1834.53 1330.86,1785 1372.86,1785 1380,1777.86 v1(1380,1766) ; v2(2217.79,2357.21) 2223.57,2363 2239.14,2363 2262,2385.86 2262,2474.86 2303.14,2516 2314.86,2516 2323.43,2507.43 2350.43,2507.43 2360.9,2517.9 2360.9,2536.24 2357.97,2539.17 2351.5,2545.64 2351.5,2554.46 2360.9,2563.86 2360.9,2667.9 2365.74,2672.74 J2.135@2365.74,2706.42
  BOTTOM w4: R122.4@980.68,1850.5 986.81,1856.63 992.47,1856.63 1006.78,1842.32 J15.29@1027.99,1842.32 1052.32,1842.32 1057.16,1847.16 1086,1847.16 v1(1093.65,1839.52) ; v1(1380,1766) 1393.09,1764.99 1422.08,1736 1443.86,1736 1466.86,1713 1626,1713 1639,1726 1639,1755 1681,1797 1681,1927 1697,1943 1697,1969 1686,1980 1686,1990.86 1697,2001.86 1697,2016 1759,2078 1759,2238 1873,2352 1919.68,2352 1929.54,2361.86 1929.54,2367 1933.54,2371 1941.54,2371 1945.54,2367 1945.54,2361.86 1955.39,2352 1971.68,2352 1981.54,2361.86 1981.54,2367 1985.54,2371 1993.54,2371 1997.54,2367 1997.54,2361.86 2007.39,2352 2023.68,2352 2033.54,2361.86 2033.54,2367 2037.54,2371 2045.54,2371 2049.54,2367 2049.54,2361.86 2059.39,2352 2075.68,2352 2085.54,2361.86 2085.54,2367 2089.54,2371 2097.54,2371 2101.54,2367 2101.54,2361.86 2111.39,2352 2127.68,2352 2137.54,2361.86 2137.54,2367 2141.54,2371 2149.54,2371 2153.54,2367 2153.54,2361.86 2163.39,2352 2193.14,2352 2204.14,2363 2212,2363 v2(2217.79,2357.21)
MIPI_DSI_TX0_D2N: D49.5 D49.6 J2.129 J15.24 R123.1 | length 2431.9
  TOP w4: v1(1095,1748) 1103.47,1739.53 1112.1,1739.53 1115,1742.43 1115,1750 1119.67,1754.67 1125.33,1754.67 1130,1750 1130,1744.53 1135,1739.53 1142.72,1739.53 1147.57,1744.37 D49.6@1167.78,1744.37 D49.5@1202.22,1744.37 1213.63,1744.37 1218.48,1739.53 1260.47,1739.53 1345,1655 1388,1655 v1(1397,1664) ; v2(2420.39,2459) 2429,2467.61 2429,2549.42 2422,2556.42 2422,2576.71 2429,2583.71 2429,2601.42 2422,2608.42 2422,2628.71 2429,2635.71 2429,2669 2424.8,2673.2 J2.129@2424.8,2706.42
  BOTTOM w4: R123.1@978.68,1734.5 985.2,1727.98 990.86,1727.98 1000.09,1737.21 1000.21,1737.21 1006.9,1743.9 J15.24@1027.99,1743.9 1059.82,1743.9 1064.66,1739.06 1086.06,1739.06 v1(1095,1748) ; v1(1397,1664) 1406,1655 1659,1655 1677,1673 1677,1729.14 1747,1799.14 1747,1954 1804,2011 1804,2216 1890,2302 2034,2302 2071,2265 2135.86,2265 2170.86,2300 2222,2300 2318,2396 2389,2396 2393,2400 2393,2410 2406,2423 2422,2423 2427,2428 2427,2452.39 v2(2420.39,2459)
MIPI_DSI_TX0_D2P: D49.4 D49.7 J2.127 J15.23 R123.2 | length 2424.3
  TOP w4: v1(1095.22,1721.22) 1103.53,1729.53 1142.72,1729.53 1147.56,1724.68 D49.7@1167.78,1724.68 D49.4@1202.22,1724.68 1215.68,1724.68 1220.52,1729.53 1256.33,1729.53 1340.86,1645 1388.71,1645 v1(1397,1636.71) ; J2.127@2444.48,2706.42 2444.48,2675.48 2439,2670 2439,2631.57 2432,2624.57 2432,2612.57 2439,2605.57 2439,2579.57 2432,2572.57 2432,2560.57 2439,2553.57 2439,2468 v2(2447,2460)
  BOTTOM w4: R123.2@978.68,1712.84 983.84,1712.84 988,1717 998,1717 1005.21,1724.21 J15.23@1027.99,1724.21 1059.82,1724.21 1064.66,1729.06 1087.38,1729.06 v1(1095.22,1721.22) ; v1(1397,1636.71) 1405.29,1645 1663.14,1645 1687,1668.86 1687,1725 1757,1795 1757,1949.86 1814,2006.86 1814,2211.86 1894.14,2292 2029.86,2292 2066.86,2255 2140,2255 2175,2290 2226.14,2290 2322.14,2386 2393.14,2386 2403,2395.86 2403,2405.86 2410.14,2413 2426.14,2413 2437,2423.86 2437,2450 v2(2447,2460)
MIPI_DSI_TX0_D3N: D49.2 D49.9 J2.125 J15.21 R123.3 | length 2517.5
  TOP w4: v1(1094,1690) 1103,1681 1116,1681 1120,1685 1120,1690 1124.67,1694.67 1130.33,1694.67 1135,1690 1135,1686 1140,1681 1150,1681 1154.32,1685.32 D49.9@1167.78,1685.32 D49.2@1202.22,1685.32 1212.68,1685.32 1217,1681 1233.14,1681 1324.14,1590 1373.73,1590 v1(1383.73,1600) ; J2.125@2464.17,2706.42 2464.17,2675.83 2468,2672 2468,2666.14 2458,2656.14 2458,2515.86 2477,2496.86 2477,2488 v2(2467,2478)
  BOTTOM w4: R123.3@978.68,1693.16 982.84,1689 993.14,1689 1000.18,1681.96 1005.04,1681.96 1007.93,1684.84 J15.21@1027.99,1684.84 1055.16,1684.84 1059,1681 1085,1681 v1(1094,1690) ; v1(1383.73,1600) 1392.37,1591.35 1397.21,1591.35 1412.86,1607 1678.86,1607 1701,1629.15 1701,1716.15 1773,1788.14 1773,1946.14 1834,2007.14 1834,2205 1909.93,2280.93 2019.07,2280.93 2060,2240 2201,2240 2332,2371 2418.86,2371 2476,2428.14 2476,2469 v2(2467,2478)
MIPI_DSI_TX0_D3P: D49.1 D49.10 J2.123 J15.20 R123.4 | length 2520.7
  TOP w4: v1(1094,1663) 1102,1671 1149,1671 1154.37,1665.63 D49.10@1167.78,1665.63 D49.1@1202.22,1665.63 1214.63,1665.63 1220,1671 1229,1671 1320,1580 1376.44,1580 v1(1383.73,1572.71) ; J2.123@2483.85,2706.42 2483.85,2674.85 2478,2669 2478,2662 2468,2652 2468,2520 2487,2501 2487,2487 v2(2497,2477)
  BOTTOM w4: R123.4@978.68,1671.5 984.76,1677.58 990.42,1677.58 1002.84,1665.16 J15.20@1027.99,1665.16 1055.16,1665.16 1061,1671 1086,1671 v1(1094,1663) ; v1(1383.73,1572.71) 1392.37,1581.35 1401.36,1581.35 1417,1597 1683,1597 1711,1625 1711,1712 1783,1784 1783,1942 1844,2003 1844,2200.86 1914.07,2270.93 2014.93,2270.93 2055.86,2230 2205.14,2230 2336.14,2361 2423,2361 2486,2424 2486,2466 v2(2497,2477)
MIPI_DSI_TX0_RST: C90.2 J15.36 R121.2 R417.2 | length 378.2
  TOP w5: v1(1073,1966) 1155,1966 1180,1991 C90.2@1180,2007.28 R417.2@1217,2007.28 1242,2032.28 1242,2118.28 R121.2@1217,2143.28
  BOTTOM w5: J15.36@1027.99,1980.12 1058.88,1980.12 v1(1073,1966)
MIPI_DSI_TX0_RST_GPIO4_C3: J2.136 R417.1 | length 1728.6
  TOP w5: R417.1@1217,2042.72 1217,2090 1139,2168 1139,2196.5 1144,2201.5 1180.5,2201.5 1181.49,2202.49 1182.04,2202.49 1306.55,2327 v1(1312,2327) ; v1(1545,2480) 1550,2475 1819,2475 v1(1830,2464) ; v1(2320,2460) 2355.9,2424.1 J2.136@2355.9,2383.58
  BOTTOM w5: v1(1312,2327) 1312,2356 1338,2382 1338,2488 1390,2540 1475,2540 1535,2480 v1(1545,2480) ; v1(1830,2464) 1836,2458 2267,2458 2284,2441 2301,2441 v1(2320,2460)
MIPI_DSI_TX1_CLKN: D37.2 D37.9 J2.96 J13.27 | length 2080.9
  TOP w4: J2.96@2749.6,2383.58 2749.6,2350.4 2754.45,2345.55 2754.45,2327.55 2902,2180 2960,2180 3126,2014 3126,1247.86 3410,963.86 3410,785 3404.68,779.68 D37.2@3404.68,767.22 D37.9@3404.68,732.78 3404.68,720.32 3410,715 3410,705.86 3447.6,668.26 3447.6,662.6 3443.11,658.11 J13.27@3443.11,632.01
MIPI_DSI_TX1_CLKP: D37.1 D37.10 J2.94 J13.26 | length 2080.4
  TOP w4: J2.94@2769.29,2383.58 2769.29,2349.29 2764.45,2344.45 2764.45,2331.7 2906.14,2190 2964.14,2190 3136,2018.14 3136,1252 3420,968 3420,785.86 3424.37,781.49 D37.1@3424.37,767.22 D37.10@3424.37,732.78 3424.37,719.37 3420,715 3420,710 3457.6,672.4 3457.6,662.4 3462.8,657.2 J13.26@3462.8,632.01
MIPI_DSI_TX1_D0N: D38.1 J2.104 J13.33 | length 2076.5
  TOP w4: J2.104@2670.86,2383.58 2670.86,2342.3 2675.71,2337.45 2675.71,2322.29 2878,2120 2935,2120 3068,1987 3068,1217.86 3315,970.86 3315,861.1 D38.1@3295,841.1 3315,821.1 3315,690.86 3329.84,676.01 3329.84,664.84 3325,660 J13.33@3325,632.01
MIPI_DSI_TX1_D0P: D36.1 J2.102 J13.32 | length 2076.5
  TOP w4: J2.102@2690.55,2383.58 2690.55,2342.3 2685.71,2337.45 2685.71,2326.44 2882.14,2130 2939.14,2130 3078,1991.14 3078,1222 3325,975 3325,861.1 D36.1@3345,841.1 3325,821.1 3325,695 3339.84,680.15 3339.84,665.16 3344.69,660.31 J13.32@3344.69,632.01
MIPI_DSI_TX1_D1N: D37.5 D37.6 J2.100 J13.30 | length 2095.5
  TOP w4: J2.100@2710.23,2383.58 2710.23,2342.3 2715.08,2337.45 2715.08,2324.92 2890,2150 2946.86,2150 3097,1999.86 3097,1233.86 3370,960.86 3370,824.14 3350.33,804.47 3350.33,785.33 3345.63,780.63 D37.5@3345.63,767.22 D37.6@3345.63,732.78 3345.63,714.37 3350.47,709.52 3350.47,697.92 3360.33,688.06 3372.79,688.06 3388.9,671.96 3388.9,663.9 3384.06,659.06 J13.30@3384.06,632.01
MIPI_DSI_TX1_D1P: D37.4 D37.7 J2.98 J13.29 | length 2095.6
  TOP w4: J2.98@2729.92,2383.58 2729.92,2342.3 2725.08,2337.45 2725.08,2329.07 2894.14,2160 2951,2160 3107,2004 3107,1238 3380,965 3380,820 3360.33,800.33 3360.33,784.67 3365.32,779.68 D37.4@3365.32,767.22 D37.7@3365.32,732.78 3365.32,715.32 3360.47,710.48 3360.47,702.06 3364.47,698.06 3376.94,698.06 3398.9,676.1 3398.9,663.1 3403.74,658.26 J13.29@3403.74,632.01
MIPI_DSI_TX1_D2N: D35.5 D35.6 J2.92 J13.24 | length 2099.5
  TOP w4: J2.92@2788.97,2383.58 2788.97,2351.03 2793.82,2346.18 2793.82,2330.18 2914,2210 2972,2210 3155,2027 3155,1260.86 3455.47,960.38 3455.47,785.48 3450.63,780.63 D35.5@3450.63,767.22 D35.6@3450.63,732.78 3450.63,719.37 3455,715 3455,705.86 3470.86,690 3488.86,690 3507.01,671.85 3507.01,662.01 3502.17,657.16 J13.24@3502.17,632.01
MIPI_DSI_TX1_D2P: D35.4 D35.7 J2.90 J13.23 | length 2099.9
  TOP w4: J2.90@2808.66,2383.58 2808.66,2353.66 2803.82,2348.82 2803.82,2334.33 2918.14,2220 2976.14,2220 3165,2031.14 3165,1265 3465.47,964.52 3465.47,784.52 3470.32,779.68 D35.4@3470.32,767.22 D35.7@3470.32,732.78 3470.32,720.32 3465,715 3465,710 3475,700 3493,700 3517.01,675.99 3517.01,662.99 3521.85,658.15 J13.23@3521.85,632.01
MIPI_DSI_TX1_D3N: D35.2 D35.9 J2.88 J13.21 | length 2108.9
  TOP w4: J2.88@2828.34,2383.58 2828.34,2351.66 2833.19,2346.81 2833.19,2332.66 2925.84,2240 2984,2240 3185,2039 3185,1275 3495,965 3495,820 3514.53,800.47 3514.53,792.28 3509.68,787.43 D35.2@3509.68,767.22 D35.9@3509.68,732.78 3509.68,720.32 3515.33,714.67 3515.33,705.53 3525.86,695 3545.86,695 3566.06,674.79 3566.06,661.06 3561.22,656.22 J13.21@3561.22,632.01
MIPI_DSI_TX1_D3P: D35.1 D35.10 J2.86 J13.20 | length 2108.3
  TOP w4: J2.86@2848.03,2383.58 2848.03,2353.03 2843.19,2348.19 2843.19,2336.8 2929.99,2250 2988.14,2250 3195,2043.14 3195,1279.14 3505,969.14 3505,824.14 3524.53,804.62 3524.53,792.28 3529.37,787.44 D35.1@3529.37,767.22 D35.10@3529.37,732.78 3529.37,719.37 3525.33,715.33 3525.33,709.67 3530,705 3550,705 3576.06,678.94 3576.06,658.94 3580.91,654.09 J13.20@3580.91,632.01
MIPI_DSI_TX1_RST: C80.2 J13.36 R98.2 R418.2 | length 316.1
  TOP w5: R418.2@3249.72,912 R98.2@3249.72,874 3249.72,871.44 C80.2@3214.28,836 3214.28,810.72 3265.95,759.05 J13.36@3265.95,632.01
MIPI_TX0_BL_PWM13: R110.2 R118.2 R138.1 U13.4 U14.2 | length 2538.8
  TOP w5: U14.2@1421.69,830 1445,830 1490,785 1568.72,785 R138.1@1597.72,814 v1(1624.86,786.86) ; U13.4@1492.4,1113.15 1525.43,1113.15 R118.2@1546.28,1134 1549.46,1134 1567.79,1152.33 1648.98,1152.33 v1(1660,1163.35) 1660.65,1164 1701,1164 1726,1189 1815,1189 1846,1220 1882,1220 1946.34,1155.66 1990.66,1155.66 2000,1165 2130,1165 2180,1215 2180,1276 2289,1385 2310,1385 2320,1395 2320,1470 2288,1502 2288,1732 2241,1779 2241,1846 2303,1908 2303,1977 2281.67,1998.33 2281.67,2139.28 2269,2151.95 R110.2@2269,2171.28
  BOTTOM w5: v1(1624.86,786.86) 1608,803.72 1608,826 1635,853 1635,908 1668,941 1668,1155.35 v1(1660,1163.35)
MIPI_TX1_BL_PWM12: R91.2 R100.2 U12.4 | length 100.5
  TOP w5: R91.2@3552.72,1270 R100.2@3552.72,1230 3565,1230 3592.4,1257.4 U12.4@3601.85,1257.4
MIPI_TX1_BL_PWM12_M0: J2.70 R91.1 | length 1506.7
  TOP w5: J2.70@3005.51,2383.58 3005.51,2339.49 3014,2331 3024,2331 3300,2055 3300,2000 3450,1850 3450,1660 3455,1655 3455,1425 3387,1357 3387,1268 3435,1220 3456,1220 3506,1270 R91.1@3517.28,1270
MIPI_TX1_RST_GPIO2_D4: J2.79
MIPI_TX1_RST_GPIO2_D6: J2.75 R418.1 | length 2405.4
  TOP w5: J2.75@2956.29,2706.42 2956.29,2643.71 2968,2632 v1(3305,2632) ; v1(3036.5,1747.5) 3036.5,1648.75 3037.65,1647.59 3037.65,1575.9 3018.87,1557.12 3018.87,1229.13 3035,1213 3035,1180 3050,1165 3062.5,1165 3112.5,1115 3112.5,1014.5 3134,993 3214.92,993 3230,977.92 3230,926.08 3215.92,912 R418.1@3214.28,912
  BOTTOM w5: v1(3036.5,1747.5) 3055,1766 3055,1792 3145,1882 3145,2240 3220,2315 3220,2355 3240,2375 3240,2567 v1(3305,2632)
N17053074: C113.2 C115.2 U18.2 | length 133
  TOP w20: U18.2@4719.41,878.27 C115.2@4810,878.28 ; C115.2@4810,878.28 4852,878.28 C113.2@4852.28,878
N17053234: C113.1 C116.2 J21.2 | length 116.4
  TOP w20: C113.1@4887.72,878 cw(c4887.72,-674.72) C116.2@4935,877.28 cw(c4935,-7657.7) J21.2@5004.13,877
N68563646: C179.2 U21.1 XT5.2 | length 206.8
  TOP w5: XT5.2@3287.79,1470 3325,1470 3330,1475 3330,1547.72 C179.2@3310,1567.72 3314.61,1572.33 U21.1@3314.61,1627.32
N68563661: C180.2 U21.2 XT5.1 | length 217.1
  TOP w5: U21.2@3340.2,1627.32 3340.2,1587.52 C180.2@3360,1567.72 3340,1547.72 3340,1475 3345,1470 XT5.1@3386.21,1470
N69300963: C2.2 D1.A F2.2 L1.1 R1.1
N69811939: C12.2 R3.1 R5.2 U1.5 | length 165.9
  TOP w10: U1.5@3009.13,2960 3020,2960 3035,2945 3035,2927.72 3025,2917.72 C12.2@3025,2907.72 R5.2@3070,2907.72 3087.28,2925 R3.1@3087.28,2948
N69812073: C1.1 L2.1 U1.2 | length 35.5
  TOP w12: 2915.78,2879 C1.1@2951.28,2879
N69812091: C1.2 U1.4 | length 70.6
  TOP w12: C1.2@2986.72,2879 2986.72,2906.72 3009.13,2929.13 U1.4@3009.13,2940.32
N69812134: C8.1 R4.1 R6.2 U1.6 | length 165.4
  TOP w12: U1.6@3009.13,2979.68 3047.97,2979.68 R4.1@3087.28,3019
  TOP w15: C8.1@3087.28,2983 R4.1@3087.28,3019 R6.2@3087.28,3054
N69812831: C13.1 L3.1 U2.2 | length 124.5
  TOP w15: 931,1277 945,1263 972,1263 1000.28,1291.28 C13.1@1038,1291.28
N69812843: C17.1 R11.1 R12.2 U2.6 | length 156.6
  TOP w12: U2.6@1064.13,1409.68 1080.32,1409.68 1095,1395
  TOP w15: 1095,1395 1120,1370 C17.1@1132.28,1370 R11.1@1132.28,1333 R12.2@1132.28,1298
N69812998: C13.2 U2.4 | length 54.4
  TOP w12: C13.2@1038,1326.72 1064.13,1352.85 U2.4@1064.13,1370.32
N69813915: R13.2 U2.5 | length 198.9
  TOP w5: U2.5@1064.13,1390 1075,1390 1100,1365 1100,1320 1085,1305 1085,1270 1095,1260 R13.2@1132.28,1260
N69814391: L4.1 U3.3
N69814410: C24.1 R15.1 R16.2 U3.5 | length 130.2
  TOP w15: C24.1@1297.72,1200 R15.1@1297.72,1240 ; R16.2@1297.72,1280 R15.1@1297.72,1240 ; U3.5@1346.85,1242.6 1300.32,1242.6 R15.1@1297.72,1240
N69814930: R14.2 U3.1 | length 65.7
  TOP w8: U3.1@1453.15,1242.6 1455.55,1242.6 1500,1198.15 R14.2@1500,1197.72
N69815076: LED1.3 R10.2 | length 226.1
  TOP w5: R10.2@3294,3275.72 3294,3295.05 3286.33,3302.72 3286.33,3486.33 LED1.3@3295,3495
N69815079: LED1.1 R8.2 | length 263.3
  TOP w5: LED1.1@3295,3595 3335,3555 3335,3475 3305,3445 R8.2@3305,3360.72
N69817092: D5.2 J4.1 R25.2 | length 248.3
  TOP w5: R25.2@2485,2872.72 2446.18,2872.72 D5.2@2440,2878.9 2420.49,2898.41 2420.49,2905.49 2430,2915 2503,2915 2543.21,2955.21 J4.1@2543.21,2978
N69817095: D6.2 J4.2 R26.2 | length 219
  TOP w5: R26.2@2345,2872.72 2383.82,2872.72 D6.2@2390,2878.9 2410,2898.9 2410,2910 2425,2925 2475,2925 2494,2944 J4.2@2494,2978
N69818339: R58.1 U8.1 | length 109.2
  TOP w10: R58.1@4360,1587.72 4360,1610 4396.7,1646.7 U8.1@4396.7,1681.7
N69818343: R55.1 U8.7 | length 98
  TOP w10: R55.1@4505,1587.72 4505,1620 4514.8,1629.8 U8.7@4514.8,1681.7
N69818347: R54.1 U8.5 | length 102.5
  TOP w10: R54.1@4455,1587.72 4455,1625 4475.5,1645.5 U8.5@4475.5,1681.7
N69818991: C44.2 R61.1 U8.39 | length 176.5
  TOP w10: C44.2@4227.56,1907 4239.46,1918.9 U8.39@4336.7,1918.9
  TOP w15: R61.1@4202.28,1855 4202.28,1881.72 C44.2@4227.56,1907
N69818999: R59.2 U8.48 | length 109.7
  TOP w10: R59.2@4246.72,1694 4261,1694 4308.7,1741.7 U8.48@4336.7,1741.7
N69819001: R65.2 U8.36 | length 204.2
  TOP w10: R65.2@4232.72,2020 4262.72,2050 4390,2050 4396.7,2043.3 U8.36@4396.7,2018.3
N69819016: R73.1 U8.28 | length 97.6
  TOP w10: U8.28@4554.2,2018.3 4554.2,2086.48 R73.1@4575,2107.28
N69819018: C45.2 U8.38 | length 139.7
  TOP w10: C45.2@4227.56,1975 4227.56,1948.6 4237.56,1938.6 U8.38@4336.7,1938.6
N69820056: R45.2 U5.3 | length 43.5
  TOP w15: U5.3@3985.6,3099.15 3987.28,3100.83 R45.2@3987.28,3142
N69820298: R51.2 U6.3 | length 51
  TOP w5: R51.2@3870,2867.72 3880.12,2857.6 U6.3@3916.85,2857.6
N69820533: R57.2 U7.4 | length 62.1
  TOP w5: U7.4@5107.4,1173.15 5131.85,1173.15 5142.72,1162.28 R57.2@5165,1162.28
N69820554: R60.2 U7.3 | length 58.6
  TOP w15: U7.3@5107.4,1066.85 5162.57,1066.85 R60.2@5165,1069.28
N69820805: R70.2 U9.4 | length 70
  TOP w5: U9.4@4481.85,647.4 4481.85,671.85 4487.72,677.72 R70.2@4487.72,715
N69820826: R72.2 U9.3 | length 111
  TOP w20: U9.3@4588.15,647.4 4607.4,647.4 4617.4,657.4 4694.88,657.4 R72.2@4695,657.28
N69821095: R77.2 U10.4 | length 88.1
  TOP w5: R77.2@4137,986.28 4137,983.55 U10.4@4197.4,923.15
N69821116: R79.2 U10.3 | length 132.2
  TOP w15: U10.3@4197.4,816.85 4197.4,802.6 4217,783 R79.2@4217,692.72
N69821410: R32.2 R36.2 U4.4 | length 111.4
  BOTTOM w5: U4.4@5092.4,2286.85 5092.4,2213.32 R36.2@5093,2212.72 R32.2@5130,2212.72
N69821431: R33.2 U4.3 | length 75.2
  BOTTOM w15: U4.3@5092.4,2393.15 5120,2393.15 5135,2378.15 R33.2@5135,2351.72
N69829177: Q1.1 Q2.3 R30.1 R31.1 R35.2 | length 218.9
  BOTTOM w10: Q1.1@4854.69,2158.5 4854.69,2174 4874.69,2194 4895,2194 4915,2214 Q2.3@4915,2221.5 4915,2254.56 4917.72,2257.28 R31.1@4917.72,2263 R30.1@4917.72,2299 4918,2298.72 R35.2@4958,2298.72
N69829182: D11.A D13.A R37.1 R38.2 R39.1 R40.2 | length 439.7
  BOTTOM w15: R39.1@4815,2352.28 4842.72,2352.28 4846.93,2348.07 D13.A@4875,2348.07 D11.A@4945,2348.07 4945,2425 4915,2455 R37.1@4915,2562.28 ; R40.2@4874,2562.72 4914.56,2562.72 R37.1@4915,2562.28 ; R38.2@4955,2562.72 4915.44,2562.72 R37.1@4915,2562.28
N69829189: C35.2 Q2.1 R35.1 R39.2 R41.2 | length 625.2
  TOP w10: v1(4702.72,2387.72) 4702.72,2326.28 4902.43,2126.57 4916.57,2126.57 4918.2,2128.2 v1(4918.2,2130)
  BOTTOM w10: v1(4918.2,2130) 4920,2130 4934.69,2144.68 Q2.1@4934.69,2158.5 4934.69,2179.68 4945.01,2190.01 4945.01,2245.01 4958,2258 R35.1@4958,2263.28
  BOTTOM w20: v1(4702.72,2387.72) R41.2@4735,2387.72 C35.2@4775,2387.72 R39.2@4815,2387.72
N69844387: C63.1 R80.2 R83.2 | length 74.8
  TOP w15: R83.2@5324.72,2719 R80.2@5324.72,2684 5325.72,2685 5363.72,2685 C63.1@5364,2685.28
N69844453: C64.1 C65.2 D29.2 J11.1 R83.1 | length 255.9
  TOP w8: C64.1@5242.72,2705 5258,2705 5272,2719 R83.1@5289.28,2719 5292.28,2722 5292.28,2748 C65.2@5299.28,2755 5300,2755.72 5300,2793.1 D29.2@5298.1,2795 5298.1,2826.9 5270,2855 J11.1@5270,2905.63
N69844782: D27.2 J10.2 R82.2 | length 429.7
  TOP w8: R82.2@5000,3272.72 5038.82,3272.72 D27.2@5040,3273.9 5040,3290 5010,3320 5010,3515 5060,3565 5060,3585.3 J10.2@5028.4,3616.9
N69844789: D28.2 J10.3 R84.2 | length 129.7
  TOP w8: R84.2@4850,3272.72 4888.82,3272.72 D28.2@4890,3273.9 4890,3328.9 J10.3@4914.2,3353.1
N69846177: C72.1 R87.1 | length 35
  TOP w8: R87.1@4780,3281.72 C72.1@4815,3281.72
N69846180: R87.2 U11.7 | length 631.2
  TOP w10: U11.7@4735,2865 4757,2865 4792,2830 4849,2830 4874,2855 4874,2920 4868,2926 4868,3129 4886,3147 4886,3177 4876,3187 4838,3187 4780,3245 R87.2@4780,3246.28
N69846237: C75.1 R88.1 | length 35
  TOP w8: R88.1@4930,3272.72 C75.1@4965,3272.72
N69846239: R88.2 U11.10 | length 497
  TOP w8: R88.2@4930,3237.28 4930,3220 4901.5,3191.5 4901.5,3140.5 4882,3121 4882,2933 4889,2926 4889,2866 4910,2845 4925,2845 4945,2865 U11.10@4975,2865
N69846282: C71.2 U11.8 | length 74.4
  TOP w15: C71.2@4662.72,2810 4667.72,2815 U11.8@4735,2815
N69846442: Q14.3 U11.5 | length 1247.8
  TOP w5: Q14.3@3647,2867.5 3665.5,2867.5 3707.91,2825.09 v1(3707.91,2789.98) ; v1(4690,2985) 4710,2965 U11.5@4735,2965
  BOTTOM w5: v1(3707.91,2789.98) 3721.89,2776 4015,2776 4074,2835 4321,2835 4356,2870 4586,2870 4690,2974 v1(4690,2985)
N69846447: Q15.3 U11.12 | length 1603.1
  TOP w5: Q15.3@3534,2870.5 3603.5,2870.5 3646.5,2827.5 3646.5,2780.5 3647.5,2779.5 v1(3647.5,2778.5) ; v1(4925,2960) 4930,2965 U11.12@4975,2965
  BOTTOM w5: v1(3647.5,2778.5) 3660,2766 4020,2766 4079,2825 4326,2825 4361,2860 4591,2860 4701,2970 4915,2970 v1(4925,2960)
N69846810: L11.1 U11.3 | length 83.7
  TOP w15: L11.1@4657.56,3080 4672.56,3065 U11.3@4735,3065
N69846813: L12.1 U11.1 | length 89.9
  TOP w15: L12.1@4657.56,3135 4687.56,3165 U11.1@4735,3165
N69846816: L13.1 U11.14 | length 92.8
  TOP w8: U11.14@4975,3065 5000,3065 5025,3090 L13.1@5057.44,3090
N69846819: L14.1 U11.16 | length 90.7
  TOP w8: U11.16@4975,3165 5000,3165 5020,3145 L14.1@5057.44,3145
N69847759: D42.C R104.2 R106.1 | length 265.8
  TOP w10: v1(3010,3081) R104.2@3010,3114.28 ; v1(3099,3093) 3100,3092 3160,3092 3176,3108 3194.09,3108 D42.C@3201,3114.91
  TOP w12: R106.1@3094,3114.28 3094,3098 v1(3099,3093)
  BOTTOM w10: v1(3010,3081) 3026,3097 3090,3097 3093,3094 3098,3094 v1(3099,3093)
N69853313: C246.1 Q12.1 R391.1 R392.1
N69853352: Q13.3 R392.2 | length 159.5
  BOTTOM w5: Q13.3@1135,2227.5 1135,2250.13 1151.13,2266.26 1166.7,2266.26 1169,2268.57 1169,2345.28 1158,2356.28 R392.2@1155,2356.28
N69854514: Q13.1 R393.1 | length 36.9
  BOTTOM w5: R393.1@1082,2288.72 1082,2286.72 1111.54,2286.72 Q13.1@1115.32,2290.5
N69857283: R172.1 R173.2 U15.4 | length 118.2
  TOP w15: U15.4@2486.17,1165.07 2486.17,1156.17 2470,1140 2460,1140 2450,1130 R173.2@2450,1107.72 R172.1@2490,1107.72
N69857307: C108.2 R175.1 R176.2 U16.4 | length 145.1
  TOP w15: R176.2@2650,1107.72 R175.1@2690,1107.72 ; U16.4@2687.6,1171.85 2687.6,1137.4 2690,1135 R175.1@2690,1107.72 ; C108.2@2730,1107.72 R175.1@2690,1107.72
N69857397: R177.1 R179.2 U17.4 | length 116.3
  TOP w15: U17.4@2905.32,1170.79 2905.32,1140.32 2895,1130 R179.2@2895,1104.72 R177.1@2941,1104.72
N69863572: C117.2 R191.1 XT2.1 | length 90.9
  TOP w10: R191.1@4795,1252.72 C117.2@4795,1292.28 4841.04,1292.28 XT2.1@4844.76,1288.57
N69863896: R209.2 R210.2 U18.34 | length 164.5
  TOP w5: R210.2@4292,692.72 R209.2@4256,692.72 4256,721 4317.83,782.83 U18.34@4317.83,795.59
N69864199: R208.2 U18.29 | length 76.3
  TOP w15: R208.2@4195,986.28 4223.72,986.28 4225.43,984.57 U18.29@4270.59,984.57
N69864441: R196.2 U18.12 | length 94.6
  TOP w5: R196.2@4656,1332.28 4656,1299 4672.17,1282.83 U18.12@4672.17,1244.41
N69864462: C127.2 C128.2 L21.2 U18.23 | length 254.4
  TOP w20: C128.2@4192.72,1220 v1(4220,1220) 4242.83,1197.17 U18.23@4270.59,1197.17
  BOTTOM w20: v1(4220,1220) 4225,1225 v1(4225,1355) v1(4225,1385)
N69864477: L21.1 U18.21
N69866041: C124.1 Q10.1 R203.1 R207.1 | length 131.3
  TOP w20: Q10.1@5147.28,1575.6 5147.87,1575 C124.1@5194.28,1575 5194.28,1590.72 5190,1595 R203.1@5190,1617.28 R207.1@5230,1617.28
N69873113: C142.2 J22.1 | length 298.5
  TOP w15: C142.2@1595,2977.72 1595,3120 v1(1600,3125)
  BOTTOM w20: J22.1@1455,3135 1590,3135 v1(1600,3125)
N69883193: C166.2 J23.1 | length 350.2
  TOP w20: C166.2@2295,2977.72 2287,2985.72 2287,3169 v1(2304.5,3186.5)
  BOTTOM w20: J23.1@2195,3135 2253,3135 v1(2304.5,3186.5)
N69887528: L24.1 U22.3
N69887530: C207.1 R343.1 R345.2 U22.5 | length 154
  BOTTOM w5: R345.2@4109,2422.28 R345.2@4110,2422.28
  BOTTOM w20: R345.2@4110,2422.28 C207.1@4147,2422.28 ; U22.5@4181.85,2367.4 4167,2367.4 4147,2387.4 C207.1@4147,2422.28 ; R343.1@4185,2422.28 C207.1@4147,2422.28
N69887600: R344.2 U22.1 | length 55.6
  BOTTOM w5: U22.1@4288.15,2367.4 4290,2369.25 R344.2@4290,2422.28
N69896427: J26.8 R333.1 | length 98.1
  TOP w20: R333.1@4875,2293.54 4875,2315 4894.3,2334.3 J26.8@4894.3,2383.6
N69897118: J26.22 R337.1 | length 139.5
  TOP w20: J26.22@4547.9,2383.6 4547.9,2340 4567.9,2320 4590,2320 4610,2300 R337.1@4610,2282.72
N69899428: J26.42 LED2.2 | length 1342.9
  TOP w12: J26.42@4232.9,2383.6 4232.9,2464 4252.9,2484 4538,2484 4560,2462 4609,2462 4650,2421 4650,2266 4820,2096 4820,2095.92 v1(4821.3,2094.62) ; v1(5119,2150.63) 5119,2168.33 5142.17,2191.5 LED2.2@5168,2191.5
  BOTTOM w12: v1(4821.3,2094.62) 4825.92,2090 5080,2090 5119,2129 v1(5119,2150.63)
N69899460: LED2.1 R342.1 | length 118
  TOP w20: R342.1@5053,2247.28 5117.78,2247.28 5125,2254.5 LED2.1@5168,2254.5
N69910248: D71.1 R330.2 SW1.3 | length 651.9
  TOP w5: R330.2@5102.72,3380 5103.9,3381.18 D71.1@5103.9,3425 5103.9,3428.1 5052,3480 5052,3513 5095,3556 5095,3670 5130,3705 5350,3705 v1(5355,3700)
  BOTTOM w5: v1(5355,3700) 5366.02,3688.98 SW1.3@5395.94,3688.98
